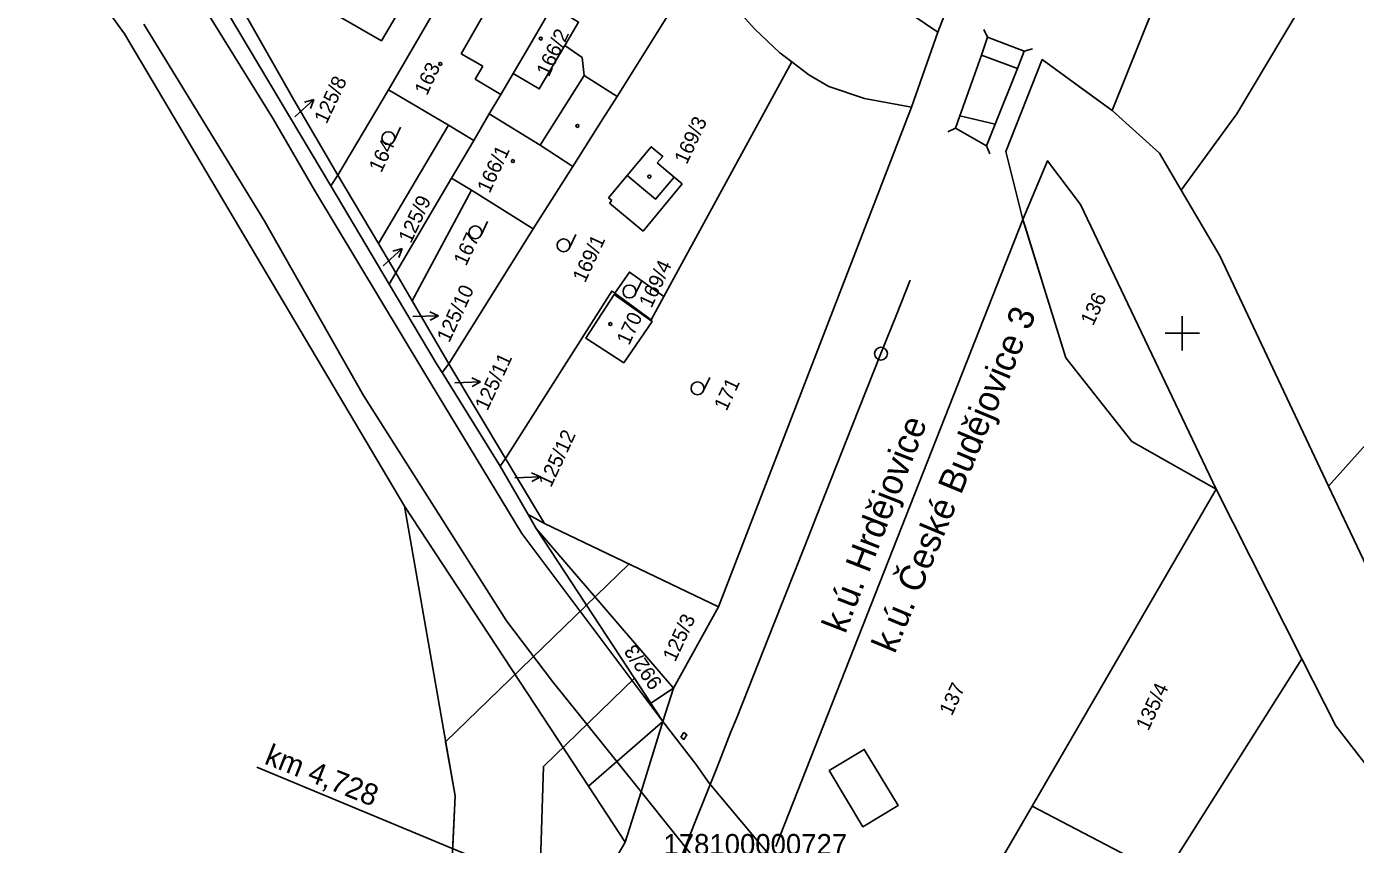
# Model space of a CAD drawing. Extents: x -755344 to -754412, y -1162670 to -1161477.
# Drawn here: x -754834.8 to -754679.8, y -1161959.6 to -1161864.3 of the extents above; entities that cross this region are included whole.
import ezdxf

# ---------------------------------------------------------------- set-up
doc = ezdxf.new("R2010")
doc.units = 0
for name, color, linetype in [('Body ŽBP', 7, 'Continuous'), ('hranice obvodu stavby', 7, 'Continuous'), ('Katastrální hranice', 7, 'Continuous'), ('Staniceni a namezniky', 7, 'Continuous'), ('Síť', 7, 'Continuous'), ('Vrstva 1', 7, 'Continuous'), ('Vrstva 12', 7, 'Continuous'), ('Vrstva 2', 7, 'Continuous'), ('Vrstva 53', 7, 'Continuous'), ('Vrstva 55', 7, 'Continuous'), ('Vrstva 56', 7, 'Continuous'), ('Vrstva 57', 7, 'Continuous'), ('Vrstva 58', 7, 'Continuous'), ('Vrstva 59', 7, 'Continuous')]:
    doc.layers.add(name, color=color, linetype=linetype)

msp = doc.modelspace()

# ---------------------------------------------------------------- linework, layer by layer
at = {"layer": 'hranice obvodu stavby'}
for points in [[(-754764.52, -1161926.91), (-754785.9, -1161947.61), (-754784.8, -1161953.94), (-754785.29, -1161964.42), (-754785.77, -1161974.89), (-754790.73, -1161989.35), (-754795.69, -1162003.82), (-754802.15, -1162019.66), (-754808.6, -1162035.49), (-754811.09, -1162040.82), (-754813.58, -1162046.15), (-754815.21, -1162048.8)], [(-754763.88, -1161940.21), (-754761.97, -1161943.12), (-754759.34, -1161941.39), (-754754.1, -1161931.89), (-754764.24, -1161927.04), (-754764.52, -1161926.91)], [(-754812.88, -1162068.75), (-754805.89, -1162053.43), (-754794.46, -1162027.05), (-754775.38, -1161978.82), (-754774.5, -1161950.49), (-754763.88, -1161940.21)]]:
    msp.add_lwpolyline(points, dxfattribs=at)
msp.add_lwpolyline([(-754741.18, -1161950.98), (-754737.08, -1161948.52), (-754733.14, -1161955.06), (-754737.24, -1161957.53)], close=True, dxfattribs=at)
at = {"layer": 'Katastrální hranice'}
for p, q in [((-754700.13, -1161883.31), (-754695.62, -1161890.99)), ((-754747.41, -1161959.83), (-754718.58, -1161886.73)), ((-754695.62, -1161890.99), (-754682.93, -1161917.84)), ((-754682.93, -1161917.84), (-754675.16, -1161934.28))]:
    msp.add_line(p, q, dxfattribs=at)
for points in [[(-754718.58, -1161886.73), (-754720.58, -1161878.83), (-754716.32, -1161868.1), (-754708.18, -1161874.05)], [(-754708.18, -1161874.05), (-754702.66, -1161879.01), (-754700.13, -1161883.31)]]:
    msp.add_lwpolyline(points, dxfattribs=at)
at = {"layer": 'Staniceni a namezniky'}
msp.add_circle((-754735.14, -1161902.38), 0.75, dxfattribs=at)
at = {"layer": 'Síť'}
for points in [[(-754700, -1161898), (-754700, -1161900), (-754700, -1161902)], [(-754698, -1161900), (-754700, -1161900), (-754702, -1161900)]]:
    msp.add_lwpolyline(points, dxfattribs=at)
at = {"layer": 'Vrstva 1'}
msp.add_lwpolyline([(-754761.68, -1161969.29), (-754760, -1161965.06), (-754759.09, -1161962.77), (-754756.79, -1161956.96), (-754754.25, -1161950.57), (-754752.63, -1161946.48), (-754752, -1161944.9), (-754751.26, -1161943.03), (-754747.59, -1161933.79), (-754744.07, -1161924.9), (-754742.14, -1161920.03), (-754738.48, -1161910.81), (-754735.14, -1161902.38), (-754733.34, -1161897.85), (-754731.73, -1161893.81)], dxfattribs=at)
at = {"layer": 'Vrstva 12'}
msp.add_lwpolyline([(-754758.48, -1161947.08), (-754758.11, -1161946.56), (-754757.76, -1161946.83), (-754758.12, -1161947.34), (-754758.48, -1161947.08)], dxfattribs=at)
at = {"layer": 'Vrstva 2'}
msp.add_line((-754761.85, -1161969.71), (-754807.93, -1161950.57), dxfattribs=at)
at = {"layer": 'Vrstva 53'}
for points in [[(-754785.77, -1161974.89), (-754784.8, -1161953.94), (-754790.69, -1161920.17), (-754769.25, -1161952.8), (-754760.56, -1161945.27), (-754775.33, -1161922.76), (-754776.28, -1161921.13), (-754774.38, -1161922.19), (-754754.1, -1161931.89), (-754731.59, -1161873.64), (-754728.5, -1161864.92), (-754709.3, -1161815.4)], [(-754695.26, -1161841.9), (-754708.18, -1161874.05), (-754711.12, -1161871.9), (-754716.32, -1161868.1), (-754720.58, -1161878.83), (-754718.58, -1161886.73), (-754718.29, -1161887.66), (-754716.05, -1161894.88), (-754713.58, -1161902.86), (-754705.88, -1161912.64), (-754696.04, -1161918.16), (-754717.5, -1161955.11), (-754731.42, -1161979.09)]]:
    msp.add_lwpolyline(points, dxfattribs=at)
at = {"layer": 'Vrstva 55'}
for p, q in [((-754708.18, -1161874.05), (-754682.98, -1161811.34)), ((-754765.9, -1161872.42), (-754756.43, -1161857.25)), ((-754813.2, -1161859.46), (-754799.29, -1161882.83)), ((-754731.59, -1161873.64), (-754728.5, -1161864.92)), ((-754760.45, -1161895.73), (-754745.52, -1161868.38)), ((-754798.49, -1161881.58), (-754792.56, -1161871.65)), ((-754754.1, -1161931.89), (-754731.59, -1161873.64)), ((-754799.29, -1161882.83), (-754798.49, -1161881.58)), ((-754798.49, -1161881.58), (-754793.74, -1161889.55)), ((-754799.29, -1161882.83), (-754792.47, -1161894.28)), ((-754700.13, -1161883.31), (-754695.62, -1161890.99)), ((-754700.13, -1161883.31), (-754695.62, -1161890.99)), ((-754747.41, -1161959.83), (-754718.58, -1161886.73)), ((-754747.41, -1161959.83), (-754718.58, -1161886.73)), ((-754785.52, -1161903.56), (-754775.69, -1161887.84)), ((-754793.74, -1161889.55), (-754791.71, -1161892.97)), ((-754695.62, -1161890.99), (-754682.93, -1161917.84)), ((-754695.62, -1161890.99), (-754682.93, -1161917.84)), ((-754792.47, -1161894.28), (-754791.71, -1161892.97)), ((-754791.71, -1161892.97), (-754789.8, -1161896.23)), ((-754789.8, -1161896.23), (-754785.52, -1161903.56)), ((-754786.32, -1161904.57), (-754785.52, -1161903.56)), ((-754785.52, -1161903.56), (-754778.9, -1161914.6)), ((-754786.32, -1161904.57), (-754779.53, -1161915.51)), ((-754682.93, -1161917.84), (-754677.24, -1161911.45)), ((-754779.53, -1161915.51), (-754778.9, -1161914.6)), ((-754778.9, -1161914.6), (-754774.38, -1161922.19)), ((-754779.53, -1161915.51), (-754776.28, -1161921.13)), ((-754682.93, -1161917.84), (-754675.16, -1161934.28)), ((-754682.93, -1161917.84), (-754675.16, -1161934.28)), ((-754696.04, -1161918.16), (-754717.5, -1161955.11)), ((-754686.04, -1161937.95), (-754696.04, -1161918.16)), ((-754769.25, -1161952.8), (-754790.69, -1161920.17)), ((-754774.38, -1161922.19), (-754776.28, -1161921.13)), ((-754776.28, -1161921.13), (-754775.33, -1161922.76)), ((-754774.38, -1161922.19), (-754754.1, -1161931.89)), ((-754775.33, -1161922.76), (-754759.34, -1161941.39)), ((-754775.33, -1161922.76), (-754760.56, -1161945.27)), ((-754759.34, -1161941.39), (-754754.1, -1161931.89)), ((-754760.56, -1161945.27), (-754759.34, -1161941.39)), ((-754764.95, -1161959.34), (-754769.25, -1161952.8)), ((-754717.5, -1161955.11), (-754731.42, -1161979.09))]:
    msp.add_line(p, q, dxfattribs=at)
for points in [[(-754790.69, -1161920.17), (-754823.33, -1161865.1), (-754831.37, -1161854.01), (-754842.43, -1161841.79), (-754855.01, -1161828.87), (-754953.69, -1161741.58)], [(-754728.5, -1161864.92), (-754738.21, -1161858.31), (-754756.21, -1161838.63), (-754776.63, -1161817.12), (-754813.94, -1161775.57)], [(-754728.5, -1161864.92), (-754704.52, -1161803.05)], [(-754700.13, -1161883.31), (-754693.64, -1161874.43), (-754682.9, -1161856.46), (-754669.27, -1161829.84), (-754663.3, -1161818.91)], [(-754797.87, -1161844.01), (-754796.07, -1161845.06), (-754795.46, -1161844.03), (-754791.02, -1161846.63), (-754794.41, -1161852.43), (-754787.75, -1161856.33), (-754793.37, -1161865.92), (-754797.77, -1161863.4), (-754800.91, -1161861.61), (-754800.98, -1161861.74), (-754801.78, -1161861.29), (-754801.71, -1161861.16), (-754806.04, -1161858.59), (-754806.12, -1161858.72), (-754806.49, -1161858.53), (-754804.23, -1161854.87), (-754797.87, -1161844.01)], [(-754792.56, -1161871.65), (-754785.42, -1161859.33), (-754783.47, -1161855.97), (-754782.47, -1161854.25)], [(-754745.52, -1161868.38), (-754746.92, -1161867.32), (-754749.85, -1161864.57), (-754756.43, -1161857.25)], [(-754812.09, -1161857.83), (-754803.59, -1161872.79), (-754798.49, -1161881.58)], [(-754778.04, -1161869.74), (-754776.09, -1161866.43), (-754773.43, -1161861.9)], [(-754772.01, -1161866.48), (-754770.39, -1161863.74), (-754773.43, -1161861.9)], [(-754772.01, -1161866.48), (-754774.99, -1161871.53), (-754778.04, -1161869.74)], [(-754765.9, -1161872.42), (-754769.74, -1161869.98), (-754769.98, -1161867.88), (-754772.01, -1161866.48)], [(-754731.59, -1161873.64), (-754737.05, -1161872.65), (-754741.21, -1161871.26), (-754743.54, -1161869.88), (-754745.52, -1161868.38)], [(-754718.58, -1161886.73), (-754720.58, -1161878.83), (-754716.32, -1161868.1), (-754708.18, -1161874.05)], [(-754718.58, -1161886.73), (-754720.58, -1161878.83), (-754716.32, -1161868.1), (-754708.18, -1161874.05)], [(-754791.71, -1161892.97), (-754785.2, -1161881.91), (-754782.63, -1161877.54), (-754780.81, -1161874.45), (-754779.48, -1161872.18), (-754778.04, -1161869.74)], [(-754792.56, -1161871.65), (-754785.56, -1161875.75), (-754793.74, -1161889.55)], [(-754775.69, -1161887.84), (-754771.06, -1161880.55), (-754767.56, -1161875.03), (-754765.9, -1161872.42)], [(-754708.18, -1161874.05), (-754702.66, -1161879.01), (-754700.13, -1161883.31)], [(-754708.18, -1161874.05), (-754702.66, -1161879.01), (-754700.13, -1161883.31)], [(-754761.24, -1161880.16), (-754759.27, -1161881.81), (-754761.41, -1161884.36), (-754764.73, -1161881.6), (-754761.92, -1161878.26), (-754760.59, -1161879.39), (-754761.24, -1161880.16)], [(-754696.04, -1161918.16), (-754711.87, -1161884.98), (-754715.72, -1161879.9), (-754718.58, -1161886.73)], [(-754789.8, -1161896.23), (-754782.9, -1161883.31), (-754775.69, -1161887.84)], [(-754718.58, -1161886.73), (-754713.58, -1161902.86), (-754705.88, -1161912.64), (-754696.04, -1161918.16)], [(-754766.16, -1161895.35), (-754764.47, -1161892.88), (-754760.45, -1161895.73)], [(-754792.47, -1161894.28), (-754786.88, -1161903.67), (-754786.32, -1161904.57)], [(-754778.9, -1161914.6), (-754766.52, -1161895.09), (-754766.16, -1161895.35)], [(-754765.12, -1161903.44), (-754761.83, -1161898.63), (-754766.26, -1161895.5), (-754769.57, -1161900.59), (-754765.12, -1161903.44)], [(-754760.45, -1161895.73), (-754761.94, -1161898.46), (-754766.16, -1161895.35)], [(-754790.69, -1161920.17), (-754784.8, -1161953.94), (-754785.77, -1161974.89), (-754795.69, -1162003.82), (-754808.6, -1162035.49), (-754813.58, -1162046.15), (-754815.21, -1162048.8)], [(-754717.5, -1161955.11), (-754702.03, -1161963.19), (-754686.04, -1161937.95)], [(-754637.39, -1161984.8), (-754642.71, -1161981.11), (-754670.75, -1161960.4), (-754682.08, -1161945.77), (-754686.04, -1161937.95)], [(-754760.56, -1161945.27), (-754765.94, -1161949.93), (-754769.25, -1161952.8)], [(-754764.95, -1161959.34), (-754763.11, -1161953.46), (-754760.56, -1161945.27)], [(-754764.95, -1161959.34), (-754780.44, -1161986.21), (-754801.36, -1162036.63)]]:
    msp.add_lwpolyline(points, dxfattribs=at)
at = {"layer": 'Vrstva 56'}
for p, q in [((-754806, -1161875.03), (-754815.09, -1161860.38)), ((-754784.08, -1161867.42), (-754781.07, -1161862.16)), ((-754821.11, -1161863.98), (-754807.06, -1161886.86)), ((-754723.15, -1161864.61), (-754722.7, -1161865.5)), ((-754722.7, -1161865.5), (-754723.43, -1161867.58)), ((-754722.7, -1161865.5), (-754718.42, -1161867.12)), ((-754717.46, -1161866.84), (-754718.42, -1161867.12)), ((-754781.58, -1161868.87), (-754784.08, -1161867.42)), ((-754723.43, -1161867.58), (-754725.93, -1161874.67)), ((-754723.43, -1161867.58), (-754719.23, -1161869.15)), ((-754718.42, -1161867.12), (-754719.23, -1161869.15)), ((-754782.45, -1161870.38), (-754781.58, -1161868.87)), ((-754769.74, -1161869.98), (-754774.88, -1161878.09)), ((-754719.23, -1161869.15), (-754721.83, -1161875.65)), ((-754782.45, -1161870.38), (-754779.48, -1161872.18)), ((-754774.88, -1161878.09), (-754780.81, -1161874.45)), ((-754801.2, -1161883.32), (-754806, -1161875.03)), ((-754782.63, -1161877.54), (-754785.56, -1161875.75)), ((-754727.35, -1161876.51), (-754726.44, -1161876.09)), ((-754725.93, -1161874.67), (-754726.44, -1161876.09)), ((-754726.44, -1161876.09), (-754722.83, -1161878.17)), ((-754725.93, -1161874.67), (-754721.83, -1161875.65)), ((-754721.83, -1161875.65), (-754722.83, -1161878.17)), ((-754774.88, -1161878.09), (-754771.06, -1161880.55)), ((-754722.44, -1161879.09), (-754722.83, -1161878.17)), ((-754785.2, -1161881.91), (-754782.9, -1161883.31)), ((-754764.73, -1161881.6), (-754766.92, -1161884.22)), ((-754758.32, -1161882.6), (-754759.27, -1161881.81)), ((-754788.45, -1161904.52), (-754801.2, -1161883.32)), ((-754762.86, -1161888.1), (-754758.32, -1161882.6)), ((-754766.92, -1161884.22), (-754766.53, -1161884.54)), ((-754766.53, -1161884.54), (-754766.81, -1161884.84)), ((-754766.81, -1161884.84), (-754762.86, -1161888.1)), ((-754807.06, -1161886.86), (-754795.46, -1161907.28)), ((-754777, -1161923.33), (-754788.45, -1161904.52)), ((-754795.46, -1161907.28), (-754778.8, -1161933.52)), ((-754760.56, -1161945.27), (-754777, -1161923.33)), ((-754778.8, -1161933.52), (-754773.44, -1161940.6)), ((-754773.44, -1161940.6), (-754765.94, -1161949.93)), ((-754756.74, -1161950.25), (-754760.56, -1161945.27)), ((-754765.94, -1161949.93), (-754763.11, -1161953.46)), ((-754755.18, -1161952.44), (-754756.74, -1161950.25)), ((-754749.74, -1161970.12), (-754763.11, -1161953.46)), ((-754747.74, -1161961.29), (-754755.18, -1161952.44))]:
    msp.add_line(p, q, dxfattribs=at)
at = {"layer": 'Vrstva 57'}
for p, q in [((-754803.49, -1161874.78), (-754801.27, -1161872.76)), ((-754801.27, -1161872.76), (-754802.35, -1161873.06)), ((-754801.27, -1161872.76), (-754801.67, -1161873.8)), ((-754793.19, -1161892.13), (-754790.97, -1161890.11)), ((-754790.97, -1161890.11), (-754792.05, -1161890.42)), ((-754790.97, -1161890.11), (-754791.37, -1161891.16)), ((-754786.72, -1161897.96), (-754787.74, -1161897.49)), ((-754789.72, -1161898.07), (-754786.72, -1161897.96)), ((-754786.72, -1161897.96), (-754787.7, -1161898.49)), ((-754781.84, -1161905.67), (-754782.85, -1161905.2)), ((-754784.84, -1161905.78), (-754781.84, -1161905.67)), ((-754781.84, -1161905.67), (-754782.82, -1161906.21)), ((-754774.85, -1161916.75), (-754775.87, -1161916.29)), ((-754777.85, -1161916.86), (-754774.85, -1161916.75)), ((-754774.85, -1161916.75), (-754775.83, -1161917.29))]:
    msp.add_line(p, q, dxfattribs=at)
at = {"layer": 'Vrstva 58'}
for p, q in [((-754791.91, -1161877.57), (-754791.17, -1161875.99)), ((-754781.76, -1161888.56), (-754781.02, -1161886.98)), ((-754771.47, -1161890.06), (-754770.73, -1161888.48)), ((-754763.78, -1161895.46), (-754763.04, -1161893.87)), ((-754755.85, -1161906.74), (-754755.11, -1161905.16))]:
    msp.add_line(p, q, dxfattribs=at)
for centre in [(-754792.59, -1161877.26), (-754782.44, -1161888.25), (-754772.15, -1161889.75), (-754764.46, -1161895.14), (-754756.53, -1161906.43)]:
    msp.add_circle(centre, 0.75, dxfattribs=at)
at = {"layer": 'Vrstva 59'}
for centre in [(-754774.81, -1161865.66), (-754786.52, -1161868.61), (-754770.53, -1161875.83), (-754778.06, -1161879.94), (-754762.14, -1161881.75), (-754766.69, -1161898.94)]:
    msp.add_circle(centre, 0.175, dxfattribs=at)

# ---------------------------------------------------------------- texts
at = {"layer": 'Body ŽBP'}
msp.add_text(' 178100000727', height=2.4, dxfattribs=at).set_placement((-754761.39, -1161960.77))
at = {"layer": 'Vrstva 2'}
msp.add_text('km 4,728', height=2.5, rotation=338.3875, dxfattribs=at).set_placement((-754807.16, -1161950.14))
at = {"layer": 'Vrstva 57'}
for s, height, rotation, p in [('166/2', 1.7, 65, (-754773.86, -1161870.2)), ('163', 1.7, 65, (-754788.08, -1161872.39)), ('125/8', 1.7, 65, (-754799.78, -1161875.7)), ('169/3', 1.7, 65, (-754757.78, -1161880.42)), ('164', 1.7, 65, (-754793.4, -1161881.38)), ('166/1', 1.7, 65, (-754780.78, -1161883.79)), ('125/9', 1.7, 65, (-754789.95, -1161889.62)), ('167', 1.7, 65, (-754783.52, -1161892.26)), ('169/1', 1.7, 65, (-754769.64, -1161894.21)), ('169/4', 1.7, 65, (-754761.9, -1161897.16)), ('125/10', 1.7, 65, (-754785.48, -1161901.18)), ('136', 1.7, 65, (-754710.4, -1161899.22)), ('170', 1.7, 65, (-754764.51, -1161901.5)), ('k.ú. České Budějovice 3', 3, 67.4059, (-754733.53, -1161937.46)), ('125/11', 1.7, 65, (-754781.03, -1161909.13)), ('171', 1.7, 65, (-754753.15, -1161909.17)), ('k.ú. Hrdějovice', 3, 68.8037, (-754739.3, -1161935.13)), ('125/12', 1.7, 65, (-754773.62, -1161918.08)), ('125/3', 1.7, 65, (-754759.13, -1161938.4)), ('992/3', 1.7, 124.9362, (-754760.55, -1161940.78)), ('137', 1.7, 65, (-754726.88, -1161944.7)), ('135/4', 1.7, 65, (-754703.96, -1161946.44))]:
    msp.add_text(s, height=height, rotation=rotation, dxfattribs=at).set_placement(p)

doc.saveas('drawing.dxf')
